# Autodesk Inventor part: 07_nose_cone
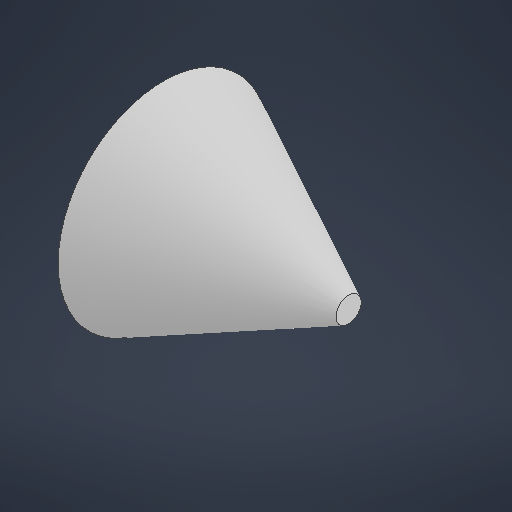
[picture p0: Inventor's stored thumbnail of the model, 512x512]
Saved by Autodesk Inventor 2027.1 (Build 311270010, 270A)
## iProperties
Created: 2026-10
Part Number: 07_nose_cone
Material: Generic
Document SubType Name: Modeling
Designer: BHAVAN KUMAR
Density: 1 g/cm^3
Appearance: Default
Author: BHAVAN KUMAR
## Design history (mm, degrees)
sketch "Sketch1"
  geometry: L1 (0, 0)-(0, 3); L2 (0, 3)-(44, 25); L3 (44, 25)-(44, 0); L4 (44, 0)-(0, 0); L5 (52.8, 0)-(-8.8, 0) reference
  constraints: 8 end point
revolve "Nose_Body" sketch "Sketch1" stored, may be unused: angle "d0" = 0 deg
sketch "Sketch10"
  geometry: C1 r 3 at (0, 0) reference; C2 r 6 at (0, 0); 1 further point
  constraints: 1 centre point, 1 coincident
  dimensions: "d17" = 12 diameter of C2
extrude "Extrusion7" cut sketch "Sketch10" distance "d18" = 30; taper "d19" = 0 deg
body "Solid1"
